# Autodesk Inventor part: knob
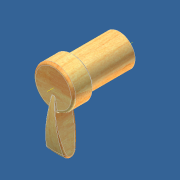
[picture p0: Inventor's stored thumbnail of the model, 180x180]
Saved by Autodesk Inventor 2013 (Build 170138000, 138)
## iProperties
Created: 2000-03
Part Number: knob
Project: 9907-000-182
Document SubType Name: Modeling
Designer: Peter Roberts
Density: 8.47 g/cm^3
Material: Brass, Soft Yellow Brass
Mass: 150.629 g
Surface Area: 47.8859 cm^2
Volume: 17.7838 cm^3
Manager: Dave Ford
Company: Autodesk Inc.
Control State: 0
Checked Out: False
Master: False
Shininess: 0.0
Length Units: 11269
Angle Units: 11279
Time Units: 11290
Mass Units: 11284
Length Display Precision: 1
Angle Display Precision: 1
Compacted: True
PropertySet Name: Model Information
Density: 0.0
Volumn: 0.0
Area: 0.0
Title: Valve Actuator
Subject: Tutorial #3 part file
Author: Peter Roberts
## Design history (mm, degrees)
node "y-z Plane"
  node "x-z Plane"
  node "x-y Plane"
node "Extrusion1" dims "d0" = 12.7, "d1" = 0
  sketch "Sketch1"
    geometry: C1 r 12.7 at (0, 0) reference
node "Extrusion2" dims "d2" = 28.75006, "d3" = 0
  sketch "Sketch2"
    geometry: C1 r 12.7 at (0, 0) reference; C2 r 10 at (0, 0)
    constraints: 1 centre point, 1 coincident
    dimensions: "d23" = 20 diameter of C2
node "Extrusion3" dims "d26" = 6, "d27" = 0
  sketch "Sketch5"
    geometry: C1 r 10 at (0, 0) reference; C2 r 3 at (0, -7)
    constraints: 1 centre point, 1 tangent
    dimensions: "d25" = 6 diameter of C2
node "Chamfer1" dims "d28" = 1, "d29" = 1, "d30" = 45 deg
node "Chamfer2" dims "d8" = 1, "d9" = 1, "d31" = 45 deg
node "Revolution1" dims "d10" = 20 deg
  sketch "Sketch4"
    geometry: L1 (0, 12.7)-(0, -16.898); A1 r 3.964 centre (-33.975, 7.901) between (-35.021, 11.725) and (-35.176, 4.123); A2 r 54.6 centre (-18.644, 56.161) between (-35.176, 4.123) and (0, 4.842); A3 r 66.365 centre (-17.524, -52.291) between (0, 11.718) and (-35.021, 11.725); 2 further points; 1 other entity
    constraints: 6 point on circle, 3 centre point, 2 end point, 2 point on line, 2 tangent, 1 vertical, 2 other
node "Fillet3" dims "d17" = 2, "d18" = 0.025
node "Fillet4" dims "d19" = 0.025, "d20" = 1.5
node "Fillet5" dims "d21" = 1.524
node "Fillet6" dims "d22" = 0.5
workaxis "Work Axis1"
body "Solid1"
